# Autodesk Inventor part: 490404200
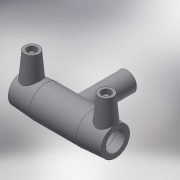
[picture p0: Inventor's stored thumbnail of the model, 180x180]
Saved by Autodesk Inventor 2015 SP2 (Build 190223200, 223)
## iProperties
Created: 2017-06
Part Number: 490404200
Material: Generic
Description: PLASSON TEE 200-200-200
Document SubType Name: Modeling
Designer: KIM
Mass: 57.3761 g
Surface Area: 241.06 cm^2
Volume: 57.3761 cm^3
Density: 1 g/cm^3
Appearance: Default
Author: KIM
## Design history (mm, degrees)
derived "490404.ipt"
feature "Solid1::490404.ipt"
tag "TaggingFeature1"
body "Solid1"
other parameters: "d0" = 451, "d2" = 261, "d3" = 114, "d4" = 112.75, "d5" = 234.9, "d8" = 168 deg, "d10" = 45.6, "d11" = 15.2, "d13" = 451, "d14" = 17.6296, "d19" = 3.52592, "d20" = 168 deg, "d22" = 242.73, "d23" = 261, "d24" = 235.4481, "d25" = 135 deg, "d26" = 315.7, "d27" = 135 deg, "d29" = 125, "d30" = 15, "d31" = 180.4, "d34" = 5 deg, "d35" = 15, "d39" = 5 deg, "d40" = 9.6, "d41" = 4.8, "d42" = 6, "d43" = 0, "d45" = 4, "d46" = 14, "d47" = 0, "d48" = -265, "d51" = 0, "d54" = 0, "d55" = 234.9, "d56" = 261, "d57" = 157.85, "d58" = 135 deg, "d59" = 114, "d60" = 114, "d61" = 135 deg, "d62" = 265, "d72" = 220.99, "d73" = 110.495, "d74" = -265, "d77" = 0, "d80" = 0, "d82" = 134.5, "d83" = 0, "d84" = 3, "d85" = 0, "d86" = 3, "d87" = 0, "d88" = 33.06, "d89" = 8.265, "d90" = 33.06, "L_" = 451, "L_1" = 114, "D_" = 261, "A_" = 125, "d_2" = 12, "H_" = 265
